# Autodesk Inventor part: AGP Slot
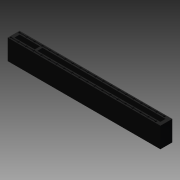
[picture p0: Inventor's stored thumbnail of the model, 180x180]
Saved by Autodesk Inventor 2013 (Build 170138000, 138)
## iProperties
Company: Autodesk Inc.
Created: 2005-12
Part Number: AGP Slot
Document SubType Name: Modeling
Designer: Autodesk Inc.
Density: 1 g/cm^3
Mass: 5.0822 g
Surface Area: 78.676 cm^2
Volume: 5.0822 cm^3
Material: Allgemein
Title: Personal Computer
Author: Autodesk Inc.
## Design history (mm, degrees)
sketch "Sketch1"
  geometry: L1 (0, 4.9)-(0, -4.9) reference; L2 (-63, 0)-(63, 0) reference; L3 (-45, 3.5)-(45, 3.5); L4 (45, 3.5)-(45, -3.5); L5 (45, -3.5)-(-45, -3.5); L6 (-45, -3.5)-(-45, 3.5)
  constraints: 8 end point, 2 parallel, 1 horizontal, 1 perpendicular, 2 other
  dimensions: "d0" = 90 distance of L3.start L3.end; "d1" = 7 distance of L5.end L3.start
extrude "Extrusion1" new body sketch "Sketch1" distance "d2" = 12; taper "d3" = 0 deg
sketch "Sketch2"
  geometry: L1 (45, 3.5)-(45, -3.5) reference; L2 (-45, -3.5)-(-45, 3.5) reference; L3 (-45, 0)-(45, 0); L4 (-43, 1.5)-(-31, 1.5); L5 (-31, 1.5)-(-31, -1.5); L6 (-31, -1.5)-(-43, -1.5); L7 (-43, -1.5)-(-43, 1.5); L8 (-29.5, 1.5)-(43, 1.5); L9 (43, 1.5)-(43, -1.5); L10 (43, -1.5)-(-29.5, -1.5); L11 (-29.5, -1.5)-(-29.5, 1.5)
  constraints: 18 end point, 4 parallel, 2 horizontal, 2 midpoint, 2 perpendicular, 1 collinear, 2 other
  dimensions: "d4" = 2 distance between parallel lines of L2 L7; "d5" = 3 distance of L6.end L4.start; "d6" = 12 distance of L4.start L4.end; "d7" = 1.5 distance between parallel lines of L11 L5; "d8" = 2 distance between parallel lines of L1 L9; "d9" = 72.5 distance of L8.start L8.end (derived)
extrude "Extrusion2" cut sketch "Sketch2" distance "d10" = 8; taper "d11" = 0 deg
sketch "Sketch3" dims "d23" = 10
  geometry: L1 (-43, 1.5)-(-31, 1.5) reference; L2 (-45, 3.5)-(45, 3.5) reference; L3 (-45, -3.5)-(-45, 3.5) reference; L4 (-27.25, 3.5)-(-27.25, 1.5); L5 (-27.25, 2.5)-(-45, 2.5); L6 (-44.5, 3)-(-43.7, 3); L7 (-43.7, 3)-(-43.7, 2); L8 (-43.7, 2)-(-44.5, 2); L9 (-44.5, 2)-(-44.5, 3); L10 (-43.5, 2.8)-(-43, 2.8); L11 (-43, 2.8)-(-43, 2.2); L12 (-43, 2.2)-(-43.5, 2.2); L13 (-43.5, 2.2)-(-43.5, 2.8); L14 (-42.8, 2.8)-(-42.3, 2.8); L15 (-42.3, 2.8)-(-42.3, 2.2); L16 (-42.8, 2.2)-(-42.8, 2.8); L17 (-42.3, 2.2)-(-42.8, 2.2); L18 (-42.1, 2.8)-(-41.6, 2.8); L19 (-41.6, 2.8)-(-41.6, 2.2); L20 (-42.1, 2.2)-(-42.1, 2.8); L21 (-41.6, 2.2)-(-42.1, 2.2); L22 (-41.4, 2.8)-(-40.9, 2.8); L23 (-40.9, 2.8)-(-40.9, 2.2); L24 (-41.4, 2.2)-(-41.4, 2.8); L25 (-40.9, 2.2)-(-41.4, 2.2); L26 (-40.7, 2.8)-(-40.2, 2.8); L27 (-40.2, 2.8)-(-40.2, 2.2); L28 (-40.7, 2.2)-(-40.7, 2.8); L29 (-40.2, 2.2)-(-40.7, 2.2)
  constraints: 52 end point, 4 parallel, 4 perpendicular, 3 horizontal, 3 point on line, 1 midpoint, 34 other
  dimensions: "d12" = 0.8 distance of L6.start L6.end; "d13" = 1 distance of L8.end L6.start; "d14" = 0.2 distance between parallel lines of L7 L13; "d15" = 0.5 distance between parallel lines of L3 L9; "d16" = 0.5 distance of L10.start L10.end; "d17" = 0.6 distance of L10.end L11.end; "d20" = 0.7 distance of L10.start L14.start
extrude "Extrusion3" cut sketch "Sketch3" distance "d25" = 5; taper "d26" = 0 deg
sketch "Sketch4"
  geometry: L1 (18.5, -2)-(19.3, -2) reference; L2 (19.3, -3)-(18.5, -3) reference; L3 (27.5, 3)-(28.3, 3) reference; L4 (28.3, 2)-(27.5, 2) reference; L5 (41, 3)-(41.8, 3); L6 (41.8, 3)-(41.8, 2); L7 (41.8, 2)-(41, 2); L8 (41, 2)-(41, 3); L9 (41, -2)-(41.8, -2); L10 (41.8, -2)-(41.8, -3); L11 (41.8, -3)-(41, -3); L12 (41, -3)-(41, -2); L13 (40.8, -2.2)-(40.8, -2.8) reference
  constraints: 16 end point, 6 collinear, 4 parallel, 2 horizontal, 2 perpendicular
  dimensions: "d34" = 0.8 distance of L10.end L11.end; "d38" = 0.2 distance between parallel lines of L13 L12
extrude "Extrusion4" cut sketch "Sketch4" distance "d35" = 8; taper "d36" = 0 deg
body "Solid1"
pattern_linear "Rectangular Pattern1" dims "d29" = 4.5, "d32" = 5
